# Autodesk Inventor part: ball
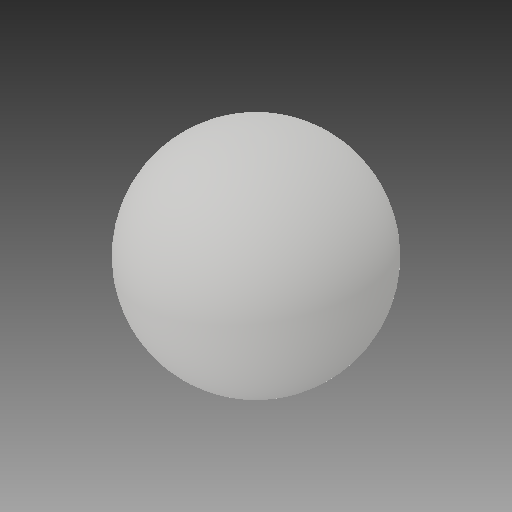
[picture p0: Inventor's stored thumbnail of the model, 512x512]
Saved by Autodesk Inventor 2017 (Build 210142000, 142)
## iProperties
Created: 2020-03
Part Number: ball
Material: Generic
Document SubType Name: Modeling
Designer: user
Density: 1 g/cm^3
Appearance: Default
Mass: 0.904779 g
Surface Area: 4.52389 cm^2
Volume: 0.904779 cm^3
Author: user
Revision Number: ANY
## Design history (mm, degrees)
feature "Revolve1"
body "Solid1"
